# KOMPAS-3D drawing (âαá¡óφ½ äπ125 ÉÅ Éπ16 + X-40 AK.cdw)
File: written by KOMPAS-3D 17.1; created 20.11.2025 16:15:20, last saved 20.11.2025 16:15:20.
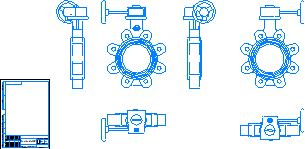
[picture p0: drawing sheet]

Sheet 1: A4, portrait

Title block, sheet 1: name: Гранвэл Ду125; material: Сталь 10  ГОСТ 1050-88; mass: 15,78; sheets: 1; sheet format: A4

Views: Вид 1, Спереди, Проекционный вид 2, Проекционный вид 3, Проекционный вид 4, Проекционный вид 5, Проекционный вид 6
Referenced files in \\adlc.lan\data\АДЛ_ПКД\3D-модели\ADL production\Дисковые поворотные затворы ГРАНВЭЛ\с резьбовыми проушинами с китайским редуктором Ру 16\KOMPAS 3D\: Гранвэл Ду125 РП Ру16 + X-40 AK.m3d
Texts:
  Andrey
  АДЛ
Dimensions and other numbers on the sheet: 1:1; 1; 15,78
